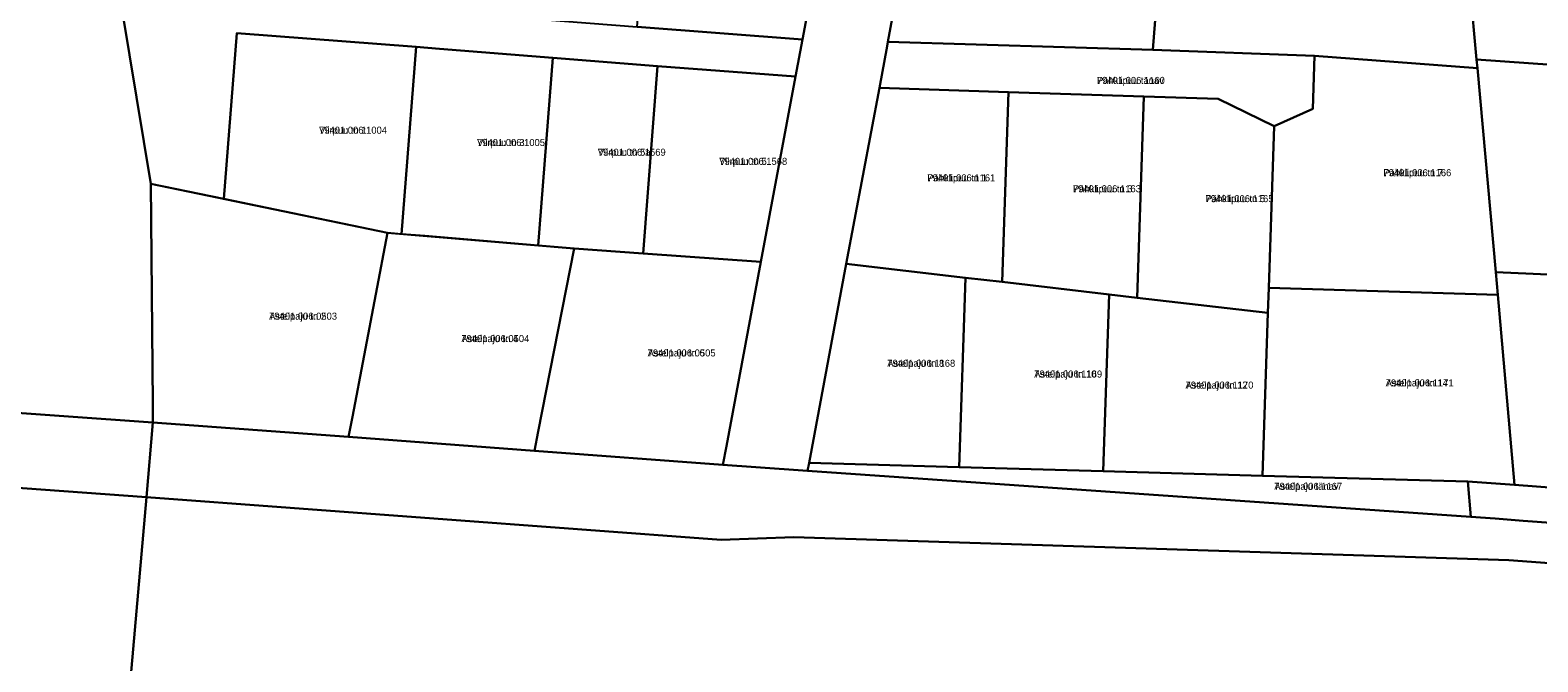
# Model space of a CAD drawing. Extents: x 625111 to 706696, y 6474150 to 6504223.
# Drawn here: x 658379.2 to 658701.1, y 6477151.9 to 6477286.7 of the extents above; entities that cross this region are included whole.
import ezdxf

# ---------------------------------------------------------------- set-up
doc = ezdxf.new("R2010")
doc.units = 0
for name, color, linetype in [('L_AADRESS', 7, 'Continuous'), ('PIIR', 7, 'Continuous'), ('TUNNUS', 7, 'Continuous')]:
    doc.layers.add(name, color=color, linetype=linetype)

msp = doc.modelspace()

# ---------------------------------------------------------------- linework, layer by layer
at = {"layer": 'PIIR'}
for points in [[(658544.09, 6477284.75), (658542.61, 6477276.81), (658513.13, 6477279.07), (658490.78, 6477280.8), (658466.6, 6477282.77), (658461.61, 6477283.14), (658423.3, 6477286.06), (658420.54, 6477250.71), (658404.94, 6477253.9), (658383.6, 6477383.09), (658396.9, 6477385.91), (658401.72, 6477356.73), (658431.31, 6477371.38), (658431.87, 6477368.87), (658402.15, 6477354.15), (658405.22, 6477335.6), (658411.94, 6477294.96), (658439.5, 6477292.8), (658471.37, 6477290.37), (658508.81, 6477287.41)], [(658295.81, 6477363.77), (658383.6, 6477383.09), (658404.94, 6477253.9), (658405.39, 6477207), (658405.42, 6477203), (658367.34, 6477205.68), (658367.27, 6477249.4), (658307.44, 6477251.12)], [(658551.48, 6477324.24), (658544.09, 6477284.75), (658508.81, 6477287.41), (658511.99, 6477327.31)], [(658685.28, 6477310.45), (658683.88, 6477325.5), (658724.02, 6477322.95), (658723.66, 6477316.23), (658721.3, 6477278.12), (658688, 6477280.44)], [(658685.28, 6477310.45), (658688, 6477280.44), (658688.23, 6477278.64), (658653.41, 6477281.24), (658618.91, 6477282.51), (658621.03, 6477309.71), (658621.46, 6477315.38)], [(658621.03, 6477309.71), (658618.91, 6477282.51), (658562.33, 6477284.26), (658567.4, 6477311.49)], [(658423.3, 6477286.06), (658461.61, 6477283.14), (658458.46, 6477243.21), (658455.51, 6477243.46), (658420.54, 6477250.71)], [(658490.78, 6477280.8), (658487.64, 6477240.78), (658463.45, 6477242.8), (658458.46, 6477243.21), (658461.61, 6477283.14), (658466.6, 6477282.77)], [(658653.41, 6477281.24), (658653.05, 6477269.91), (658644.76, 6477266.26), (658632.83, 6477272.05), (658616.96, 6477272.56), (658588.08, 6477273.51), (658560.56, 6477274.44), (658562.14, 6477283.35), (658562.33, 6477284.26), (658618.91, 6477282.51)], [(658490.78, 6477280.8), (658513.13, 6477279.07), (658510.05, 6477239.08), (658495.36, 6477240.14), (658487.64, 6477240.78)], [(658513.13, 6477279.07), (658542.61, 6477276.81), (658535.22, 6477237.27), (658510.05, 6477239.08)], [(658688.23, 6477278.64), (658692.15, 6477235.06), (658692.57, 6477230.24), (658643.64, 6477231.71), (658644.76, 6477266.26), (658653.05, 6477269.91), (658653.41, 6477281.24)], [(658688.23, 6477278.64), (658688, 6477280.44), (658721.3, 6477278.12), (658737.93, 6477276.33), (658734.12, 6477232.04), (658730.21, 6477187.13), (658725.22, 6477187.5), (658728.77, 6477233.47), (658692.15, 6477235.06)], [(658588.08, 6477273.51), (658586.72, 6477232.98), (658578.9, 6477233.86), (658553.43, 6477236.86), (658560.56, 6477274.44)], [(658616.96, 6477272.56), (658615.55, 6477229.58), (658609.57, 6477230.29), (658586.72, 6477232.98), (658588.08, 6477273.51)], [(658644.76, 6477266.26), (658643.64, 6477231.71), (658643.46, 6477226.36), (658615.55, 6477229.58), (658616.96, 6477272.56), (658632.83, 6477272.05)], [(658448.02, 6477204.16), (658447.18, 6477199.93), (658405.42, 6477203), (658405.39, 6477207), (658404.94, 6477253.9), (658455.51, 6477243.46)], [(658487.65, 6477201.09), (658486.87, 6477196.96), (658447.18, 6477199.93), (658448.02, 6477204.16), (658455.51, 6477243.46), (658495.36, 6477240.14)], [(658527.86, 6477197.92), (658527.12, 6477193.96), (658486.87, 6477196.96), (658487.65, 6477201.09), (658495.36, 6477240.14), (658510.05, 6477239.08), (658535.22, 6477237.27)], [(658578.9, 6477233.86), (658577.57, 6477193.47), (658545.49, 6477194.4), (658553.43, 6477236.86)], [(658609.57, 6477230.29), (658608.28, 6477192.56), (658577.57, 6477193.47), (658578.9, 6477233.86), (658586.72, 6477232.98)], [(658692.57, 6477230.24), (658692.15, 6477235.06), (658728.77, 6477233.47), (658725.22, 6477187.5), (658696.1, 6477189.64)], [(658643.46, 6477226.36), (658642.31, 6477191.57), (658608.28, 6477192.56), (658609.57, 6477230.29), (658615.55, 6477229.58)], [(658692.57, 6477230.24), (658696.1, 6477189.64), (658686.13, 6477190.41), (658642.31, 6477191.57), (658643.46, 6477226.36), (658643.64, 6477231.71)], [(658311.73, 6477209.56), (658334.49, 6477207.97), (658367.34, 6477205.68), (658405.42, 6477203), (658404.01, 6477187.04), (658311.84, 6477193.71)], [(658404.01, 6477187.04), (658405.42, 6477203), (658447.18, 6477199.93), (658486.87, 6477196.96), (658527.12, 6477193.96), (658534.1, 6477193.43), (658545.15, 6477192.65), (658686.78, 6477182.82), (658692, 6477182.49), (658697.98, 6477182), (659022.98, 6477158.48), (659034.25, 6477157.62), (659041.31, 6477128.02), (659009.66, 6477150.34), (658694.91, 6477173.6), (658542.28, 6477178.48), (658526.7, 6477177.95)], [(658311.84, 6477193.71), (658404.01, 6477187.04), (658400.11, 6477142.41), (658388.77, 6477016.74), (658313.18, 6477009.51)], [(658686.13, 6477190.41), (658686.78, 6477182.82), (658545.15, 6477192.65), (658545.49, 6477194.4), (658577.57, 6477193.47), (658608.28, 6477192.56), (658642.31, 6477191.57)], [(658686.78, 6477182.82), (658686.13, 6477190.41), (658696.1, 6477189.64), (658725.22, 6477187.5), (658730.21, 6477187.13), (658735.17, 6477186.76), (658771.18, 6477184.08), (658826.66, 6477180), (658839.65, 6477179.02), (658861.41, 6477177.43), (658927.74, 6477172.5), (658942.08, 6477171.43), (658990.69, 6477167.84), (659018.49, 6477177.34), (659022.98, 6477158.48), (658697.98, 6477182), (658692, 6477182.49)]]:
    msp.add_lwpolyline(points, close=True, dxfattribs=at)
for points in [[(658567.4, 6477311.49), (658562.33, 6477284.26), (658562.14, 6477283.35), (658560.56, 6477274.44), (658553.43, 6477236.86), (658545.49, 6477194.4), (658545.15, 6477192.65), (658534.1, 6477193.43), (658527.12, 6477193.96), (658527.86, 6477197.92), (658535.22, 6477237.27), (658542.61, 6477276.81), (658544.09, 6477284.75), (658551.48, 6477324.24)], [(658704.28, 6477028.7), (658616.59, 6477042.29), (658602.1, 6476951.96), (658559.2, 6476964.51), (658497.21, 6476982.72), (658524.3, 6477145.29), (658400.11, 6477142.41), (658404.01, 6477187.04), (658526.7, 6477177.95), (658542.28, 6477178.48), (658694.91, 6477173.6), (659009.66, 6477150.34)]]:
    msp.add_lwpolyline(points, dxfattribs=at)

# ---------------------------------------------------------------- texts
at = {"layer": 'L_AADRESS'}
for s, p in [('Pähklipuu tänav', (658606.96, 6477275.26)), ('Viirpuu tn 1', (658440.89, 6477264.63)), ('Viirpuu tn 3', (658474.62, 6477261.99)), ('Viirpuu tn 5a', (658500.39, 6477259.92)), ('Viirpuu tn 5', (658526.33, 6477257.98)), ('Pähklipuu tn 1', (658570.75, 6477254.46)), ('Pähklipuu tn 7', (658668.11, 6477255.56)), ('Pähklipuu tn 3', (658601.84, 6477252.13)), ('Pähklipuu tn 5', (658630.15, 6477250.02)), ('Astelpaju tn 2', (658430.22, 6477224.93)), ('Astelpaju tn 4', (658471.27, 6477220.14)), ('Astelpaju tn 6', (658511.04, 6477217.08)), ('Astelpaju tn 8', (658562.2, 6477214.87)), ('Astelpaju tn 10', (658593.57, 6477212.58)), ('Astelpaju tn 12', (658625.87, 6477210.22)), ('Astelpaju tn 14', (658668.61, 6477210.68)), ('Astelpaju tänav', (658644.82, 6477188.61))]:
    msp.add_text(s, height=1.5, dxfattribs=at).set_placement(p)
at = {"layer": 'TUNNUS'}
for s, p in [('79401:006:1160', (658606.96, 6477275.26)), ('79401:006:1004', (658440.89, 6477264.63)), ('79401:006:1005', (658474.62, 6477261.99)), ('79401:006:1569', (658500.39, 6477259.92)), ('79401:006:1568', (658526.33, 6477257.98)), ('79401:006:1161', (658570.75, 6477254.46)), ('79401:006:1166', (658668.11, 6477255.56)), ('79401:006:1163', (658601.84, 6477252.13)), ('79401:006:1165', (658630.15, 6477250.02)), ('79401:006:0503', (658430.22, 6477224.93)), ('79401:006:0504', (658471.27, 6477220.14)), ('79401:006:0505', (658511.04, 6477217.08)), ('79401:006:1168', (658562.2, 6477214.87)), ('79401:006:1169', (658593.57, 6477212.58)), ('79401:006:1170', (658625.87, 6477210.22)), ('79401:006:1171', (658668.61, 6477210.68)), ('79401:006:1167', (658644.82, 6477188.61))]:
    msp.add_text(s, height=1.5, dxfattribs=at).set_placement(p)

doc.saveas('drawing.dxf')
